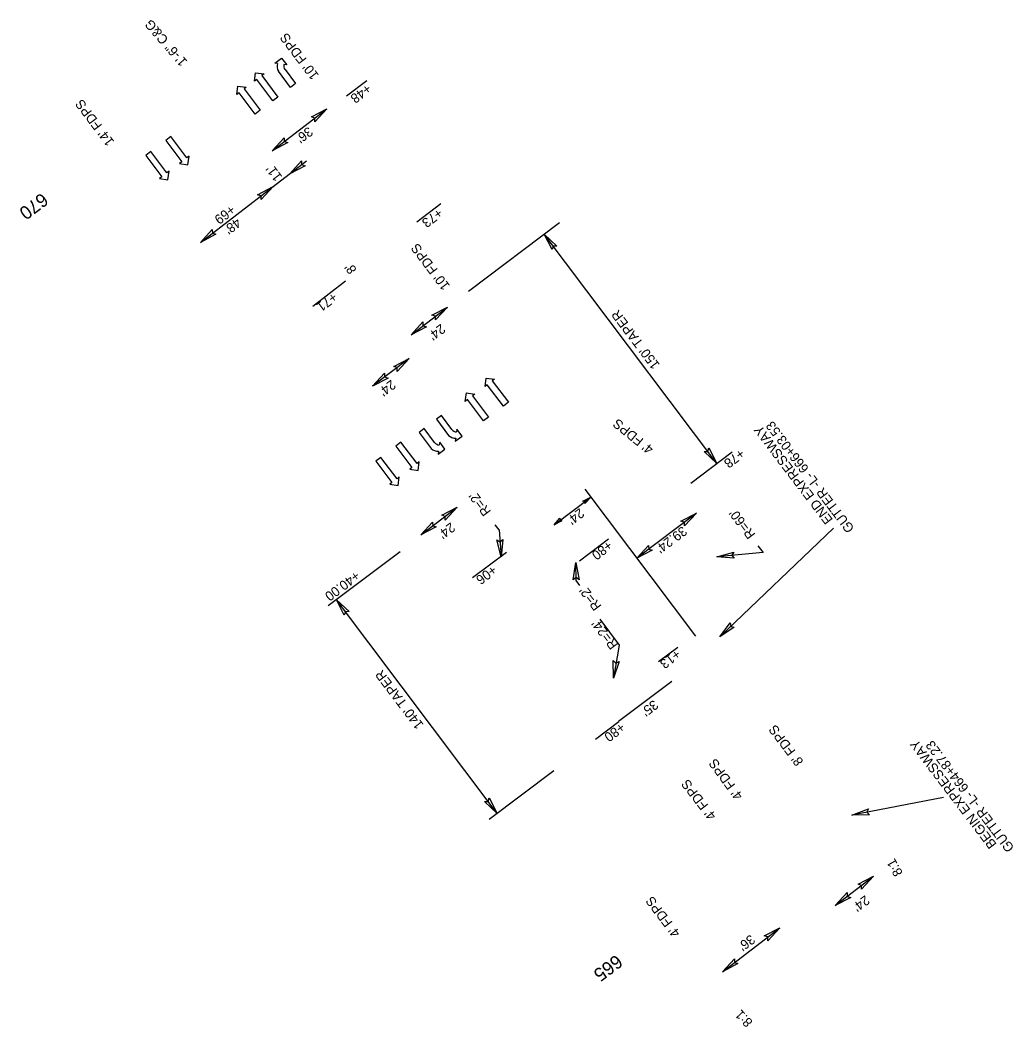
# Model space of a CAD drawing. Extents: x 1262692 to 1264138, y 775643 to 777474.
# Drawn here: x 1263618 to 1264138, y 775643 to 776170 of the extents above; entities that cross this region are included whole.
import ezdxf

# ---------------------------------------------------------------- set-up
doc = ezdxf.new("R2010")
doc.units = 0
for name, color, linetype in [('Prop Dimension', 7, 'Continuous'), ('Prop Dimension Text', 7, 'Continuous'), ('Prop Horizontal Alignment Tick Label', 7, 'Continuous'), ('Prop Lane Arrow CELL', 7, 'Continuous'), ('Prop Lane Lines', 7, 'Continuous'), ('Prop Terminator CELL', 7, 'Continuous')]:
    doc.layers.add(name, color=color, linetype=linetype)

msp = doc.modelspace()

# ---------------------------------------------------------------- linework, layer by layer
at = {"layer": 'Prop Dimension'}
for p, q in [((1263788.8, 776130.73), (1263799.38, 776138.85)), ((1263749.92, 776101.96), (1263778.46, 776123.9)), ((1263750.3, 776083.15), (1263767.8, 776096.61)), ((1263712.26, 776053.9), (1263750.3, 776083.15)), ((1263825.66, 776064.61), (1263838.16, 776074.22)), ((1263852.69, 776028.36), (1263900.37, 776064.28)), ((1263914.8, 776028.49), (1263892.38, 776058.26)), ((1263771.15, 776020.58), (1263788.29, 776033.75)), ((1263958.44, 775970.56), (1263914.8, 776028.49)), ((1263822.63, 776005.43), (1263841.66, 776020.06)), ((1263982.9, 775938.08), (1263958.44, 775970.56)), ((1263969.21, 775927.77), (1263990.89, 775944.09)), ((1263827.7, 775900.63), (1263846.87, 775915.07)), ((1263972.21, 775912.02), (1263940.88, 775888.4)), ((1264043.97, 775904.2), (1263984.45, 775847.18)), ((1263816.85, 775891.79), (1263779.23, 775863.45)), ((1263854.9, 775878.31), (1263872.62, 775891.65)), ((1263867.83, 775754.67), (1263783.48, 775866.65)), ((1263921.54, 775856.48), (1263931.79, 775842.86)), ((1263931.79, 775842.86), (1263928.68, 775825.6)), ((1263931.54, 775802.66), (1263919.25, 775793.41)), ((1263897.47, 775777), (1263863.57, 775751.47)), ((1264101.6, 775762.94), (1264053.71, 775753.74)), ((1264044.95, 775706.34), (1264064.98, 775721.74)), ((1263985.88, 775671.67), (1264015.84, 775694.7))]:
    msp.add_line(p, q, dxfattribs=at)
msp.add_lwpolyline([(1263901.62, 775908.04), (1263897.57, 775905.93), (1263900.69, 775909.31), (1263900.72, 775908.32)], close=True, dxfattribs=at)
at = {"layer": 'Prop Dimension Text'}
for p, q in [((1263821.65, 775993.06), (1263802.48, 775978.63)), ((1263897.57, 775905.93), (1263916.77, 775920.39)), ((1263868.81, 775903.25), (1263866.79, 775905.92)), ((1263868.81, 775903.25), (1263866.79, 775905.92)), ((1263868.81, 775903.25), (1263869.82, 775889.19)), ((1263910.83, 775887.08), (1263926.11, 775898.59)), ((1264004.46, 775894.93), (1264007.16, 775891.33)), ((1263909.11, 775876.8), (1263909.04, 775886.11)), ((1264007.16, 775891.33), (1263982.88, 775889.07)), ((1263911.13, 775874.12), (1263909.11, 775876.8)), ((1263952.24, 775834.22), (1263962.37, 775841.85)), ((1263959.38, 775823.87), (1263931.42, 775802.82))]:
    msp.add_line(p, q, dxfattribs=at)
for points in [[(1263912.72, 775918.28), (1263916.77, 775920.39), (1263913.65, 775917.01), (1263913.62, 775918)], [(1263787.66, 775858.53), (1263783.48, 775866.65), (1263790.2, 775860.39), (1263788.23, 775860.34)], [(1263863.65, 775762.79), (1263867.83, 775754.67), (1263861.1, 775760.94), (1263863.07, 775760.98)]]:
    msp.add_lwpolyline(points, close=True, dxfattribs=at)
at = {"layer": 'Prop Lane Arrow CELL'}
for p, q in [((1263751.24, 776147.83), (1263754.73, 776150.52)), ((1263754.73, 776150.52), (1263757.47, 776146.95)), ((1263752.71, 776147.62), (1263751.24, 776147.83)), ((1263757.47, 776146.95), (1263756, 776147.16)), ((1263740.62, 776138.42), (1263741.2, 776142.8)), ((1263741.82, 776139.32), (1263740.62, 776138.42)), ((1263741.2, 776142.8), (1263745.65, 776142.21)), ((1263750.24, 776128.14), (1263741.82, 776139.32)), ((1263745.65, 776142.21), (1263744.46, 776141.31)), ((1263744.46, 776141.31), (1263752.88, 776130.12)), ((1263759.46, 776135.18), (1263753.11, 776143.61)), ((1263756.59, 776144.47), (1263762.09, 776137.16)), ((1263731.28, 776131.48), (1263731.86, 776135.86)), ((1263731.86, 776135.86), (1263736.31, 776135.27)), ((1263736.31, 776135.27), (1263735.11, 776134.37)), ((1263735.11, 776134.37), (1263743.53, 776123.18)), ((1263762.09, 776137.16), (1263759.46, 776135.18)), ((1263732.47, 776132.38), (1263731.28, 776131.48)), ((1263740.9, 776121.2), (1263732.47, 776132.38)), ((1263752.88, 776130.12), (1263750.24, 776128.14)), ((1263743.53, 776123.18), (1263740.9, 776121.2)), ((1263696.67, 776109.36), (1263694.04, 776107.37)), ((1263705.09, 776098.18), (1263696.67, 776109.36)), ((1263694.04, 776107.37), (1263702.46, 776096.19)), ((1263686.2, 776101.47), (1263683.56, 776099.48)), ((1263683.56, 776099.48), (1263691.98, 776088.3)), ((1263694.62, 776090.29), (1263686.2, 776101.47)), ((1263706.29, 776099.08), (1263705.09, 776098.18)), ((1263705.63, 776094.64), (1263706.29, 776099.08)), ((1263702.46, 776096.19), (1263701.26, 776095.29)), ((1263701.26, 776095.29), (1263705.63, 776094.64)), ((1263691.98, 776088.3), (1263690.79, 776087.4)), ((1263690.79, 776087.4), (1263695.16, 776086.75)), ((1263695.82, 776091.19), (1263694.62, 776090.29)), ((1263695.16, 776086.75), (1263695.82, 776091.19)), ((1263861.4, 775978.4), (1263861.98, 775982.79)), ((1263861.98, 775982.79), (1263866.43, 775982.19)), ((1263866.43, 775982.19), (1263865.23, 775981.29)), ((1263865.23, 775981.29), (1263873.65, 775970.11)), ((1263862.59, 775979.31), (1263861.4, 775978.4)), ((1263871.02, 775968.12), (1263862.59, 775979.31)), ((1263851.04, 775970.61), (1263851.62, 775974.99)), ((1263852.24, 775971.51), (1263851.04, 775970.61)), ((1263851.62, 775974.99), (1263856.08, 775974.4)), ((1263860.67, 775960.33), (1263852.24, 775971.51)), ((1263856.08, 775974.4), (1263854.88, 775973.49)), ((1263854.88, 775973.49), (1263863.3, 775962.31)), ((1263873.65, 775970.11), (1263871.02, 775968.12)), ((1263838.56, 775963.17), (1263835.92, 775961.19)), ((1263835.92, 775961.19), (1263842.27, 775952.76)), ((1263844.06, 775955.87), (1263838.56, 775963.17)), ((1263863.3, 775962.31), (1263860.67, 775960.33)), ((1263829.5, 775956.35), (1263826.87, 775954.37)), ((1263835.01, 775949.04), (1263829.5, 775956.35)), ((1263846.69, 775956.03), (1263846.48, 775954.56)), ((1263849.36, 775952.41), (1263846.69, 775956.03)), ((1263826.87, 775954.37), (1263833.21, 775945.94)), ((1263845.81, 775949.8), (1263849.36, 775952.41)), ((1263846.02, 775951.27), (1263845.81, 775949.8)), ((1263817.33, 775949.16), (1263814.7, 775947.18)), ((1263814.7, 775947.18), (1263823.12, 775935.99)), ((1263825.76, 775937.98), (1263817.33, 775949.16)), ((1263836.76, 775942.98), (1263840.3, 775945.59)), ((1263836.97, 775944.45), (1263836.76, 775942.98)), ((1263837.64, 775949.21), (1263837.43, 775947.74)), ((1263840.3, 775945.59), (1263837.64, 775949.21)), ((1263806.86, 775941.27), (1263804.22, 775939.29)), ((1263804.22, 775939.29), (1263812.65, 775928.1)), ((1263815.28, 775930.09), (1263806.86, 775941.27)), ((1263826.96, 775938.88), (1263825.76, 775937.98)), ((1263826.3, 775934.44), (1263826.96, 775938.88)), ((1263823.12, 775935.99), (1263821.92, 775935.09)), ((1263821.92, 775935.09), (1263826.3, 775934.44)), ((1263816.48, 775930.99), (1263815.28, 775930.09)), ((1263815.82, 775926.55), (1263816.48, 775930.99)), ((1263812.65, 775928.1), (1263811.45, 775927.2)), ((1263811.45, 775927.2), (1263815.82, 775926.55))]:
    msp.add_line(p, q, dxfattribs=at)
for centre, radius, start, end in [((1263757.72, 776146.09), 5.25, 162.9996, 208.3113), ((1263759.18, 776146.44), 3.27, 167.3292, 216.9874), ((1263846.67, 775957.82), 3.27, 216.9874, 266.6456), ((1263845.93, 775956.51), 5.25, 225.6635, 270.9752), ((1263836.87, 775949.69), 5.25, 225.6635, 270.9752), ((1263837.62, 775951), 3.27, 216.9874, 266.6456)]:
    msp.add_arc(centre, radius, start, end, dxfattribs=at)
at = {"layer": 'Prop Lane Lines'}
msp.add_line((1263913.64, 775924.53), (1263971.64, 775847.6), dxfattribs=at)
at = {"layer": 'Prop Terminator CELL'}
for points in [[(1263770.38, 776119.65), (1263778.46, 776123.9), (1263772.26, 776117.12), (1263772.2, 776119.09)], [(1263758, 776106.22), (1263749.92, 776101.96), (1263756.12, 776108.74), (1263756.18, 776106.78)], [(1263767.11, 776094.12), (1263759.03, 776089.86), (1263765.23, 776096.65), (1263765.3, 776094.68)], [(1263742.23, 776078.9), (1263750.31, 776083.15), (1263744.11, 776076.37), (1263744.04, 776078.34)], [(1263720.34, 776058.16), (1263712.26, 776053.9), (1263718.46, 776060.68), (1263718.52, 776058.72)], [(1263896.56, 776050.14), (1263892.38, 776058.26), (1263899.1, 776051.99), (1263897.13, 776051.95)], [(1263833.58, 776015.8), (1263841.66, 776020.06), (1263835.46, 776013.27), (1263835.4, 776015.24)], [(1263830.71, 776009.68), (1263822.63, 776005.43), (1263828.83, 776012.21), (1263828.89, 776010.24)], [(1263813.53, 775988.89), (1263821.65, 775993.06), (1263815.39, 775986.34), (1263815.34, 775988.31)], [(1263810.6, 775982.8), (1263802.48, 775978.63), (1263808.75, 775985.35), (1263808.79, 775983.38)], [(1263978.73, 775946.2), (1263982.9, 775938.08), (1263976.18, 775944.34), (1263978.15, 775944.39)], [(1263838.75, 775910.9), (1263846.87, 775915.07), (1263840.6, 775908.35), (1263840.56, 775910.32)], [(1263835.82, 775904.81), (1263827.7, 775900.63), (1263833.96, 775907.36), (1263834.01, 775905.39)], [(1263964.09, 775907.84), (1263972.21, 775912.02), (1263965.95, 775905.29), (1263965.9, 775907.26)], [(1263870.72, 775898.28), (1263869.82, 775889.19), (1263867.57, 775898.1), (1263869.25, 775897.07)], [(1263949, 775892.58), (1263940.88, 775888.4), (1263947.14, 775895.12), (1263947.18, 775893.15)], [(1263991.98, 775888.36), (1263982.88, 775889.07), (1263991.74, 775891.51), (1263990.75, 775889.81)], [(1263907.56, 775877.1), (1263909.04, 775886.11), (1263910.71, 775877.08), (1263909.1, 775878.21)], [(1263992.02, 775852.29), (1263984.45, 775847.18), (1263989.87, 775854.59), (1263990.15, 775852.64)], [(1263931.72, 775834.22), (1263928.68, 775825.6), (1263928.62, 775834.79), (1263930.01, 775833.39)], [(1264062.84, 775753.92), (1264053.71, 775753.74), (1264062.29, 775757.02), (1264061.47, 775755.23)], [(1264056.9, 775717.49), (1264064.98, 775721.74), (1264058.78, 775714.96), (1264058.72, 775716.93)], [(1264053.03, 775710.6), (1264044.95, 775706.34), (1264051.15, 775713.12), (1264051.21, 775711.15)], [(1264007.76, 775690.44), (1264015.84, 775694.7), (1264009.64, 775687.92), (1264009.58, 775689.89)], [(1263993.96, 775675.92), (1263985.88, 775671.67), (1263992.08, 775678.45), (1263992.14, 775676.48)]]:
    msp.add_lwpolyline(points, close=True, dxfattribs=at)

# ---------------------------------------------------------------- texts
at = {"layer": 'Prop Dimension'}
for s, rotation, p in [("11'", 126.9874, (1263755.43, 776088.25)), ("8'", 126.9874, (1263794.41, 776039.67)), ('GUTTER -L- 666+03.53', 127.2344, (1264055.21, 775904.06)), ('END EXPRESSWAY', 127.2344, (1264043.92, 775908.6)), ("R=2'", 126.9874, (1263864.77, 775912.87)), ("R=60'", 126.9874, (1264003.37, 775900.86)), ("R=2'", 126.9874, (1263922.69, 775863.31)), ("R=24'", 126.9874, (1263931.33, 775842.99)), ('BEGIN EXPRESSWAY', 127.2344, (1264129.76, 775738.53)), ('GUTTER -L- 664+87.23', 127.2344, (1264139.01, 775736.69))]:
    msp.add_text(s, height=5, rotation=rotation, dxfattribs=at).set_placement(p)
at = {"layer": 'Prop Dimension Text'}
for s, rotation, p in [('1\'-6" C&G', 130.703, (1263705.7, 776148.81)), ("10' FDPS", 126.9874, (1263774.59, 776141.47)), ('+48', 216.7165, (1263799.49, 776137.25)), ("14' FDPS", 126.9874, (1263667.34, 776106.72)), ("36'", 216.7165, (1263768.83, 776114.8)), ('+69', 216.7165, (1263728.21, 776073.82)), ("48'", 216.7165, (1263731.22, 776067.03)), ('+73', 216.7165, (1263836.92, 776072.06)), ("10' FDPS", 126.9874, (1263843.26, 776031.18)), ('+71', 216.7165, (1263781.71, 776028.04)), ("150' TAPER", 126.9874, (1263953.21, 775989.8)), ("24'", 216.7165, (1263838.27, 776011.44)), ("24'", 217.2584, (1263812.26, 775982.17)), ("4' FDPS", 140.9826, (1263950.17, 775946.34)), ('+78', 216.9874, (1263995.18, 775946.04)), ("24'", 217.2584, (1263911.01, 775914.84)), ("24'", 216.7165, (1263843.41, 775907.38)), ("39.24'", 216.9874, (1263964.87, 775905.45)), ('+80', 217.2584, (1263925.86, 775897.92)), ('+06', 216.7165, (1263865.27, 775885.02)), ('+40.00', 216.9874, (1263793.49, 775881.99)), ('+13', 216.7165, (1263961.64, 775840.89)), ("140' TAPER", 126.9874, (1263829.46, 775801.13)), ("35'", 217.2584, (1263949.79, 775814.39)), ('+80', 216.7165, (1263932.48, 775802.57)), ("8' FDPS", 126.9874, (1264028.52, 775781.86)), ("4' FDPS", 126.2139, (1263996.86, 775763.92)), ("4' FDPS", 127.6193, (1263982.88, 775753.46)), ('8:1', 119.4231, (1264080.51, 775723.4)), ("4' FDPS", 126.9874, (1263964.03, 775691.99)), ("24'", 216.7165, (1264060.63, 775711.98)), ("36'", 216.7165, (1264000.58, 775691.43)), ('8:1', 134.3594, (1264002.03, 775645.55))]:
    msp.add_text(s, height=5, rotation=rotation, dxfattribs=at).set_placement(p)
at = {"layer": 'Prop Horizontal Alignment Tick Label'}
for s, p in [('670', (1263629.1, 776080.26)), ('665', (1263930.12, 775681.02))]:
    msp.add_text(s, height=7, rotation=216.9874, dxfattribs=at).set_placement(p)

doc.saveas('drawing.dxf')
